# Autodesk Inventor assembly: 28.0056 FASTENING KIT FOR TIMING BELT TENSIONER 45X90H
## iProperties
Created: 2007-06
Part Number: 28.0056 FASTENING KIT FOR TIMING BELT TENSIONER 45X90H
Document SubType Name: Assembly
Designer: Andy Moles
Author: Andy Moles
